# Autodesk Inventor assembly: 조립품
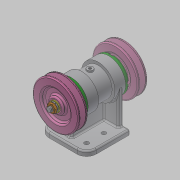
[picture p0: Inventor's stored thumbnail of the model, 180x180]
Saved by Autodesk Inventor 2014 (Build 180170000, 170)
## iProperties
Created: 2020-06
Part Number: 조립품
Document SubType Name: Assembly
Designer: NET
Author: NET
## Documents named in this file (12)
- C:\Users\NET\Desktop\700606V1053\조립품.iam
- C:\Users\NET\Desktop\700606V1053\본체.ipt
- C:\Users\NET\Desktop\700606V1053\V-벨트풀리.ipt
- C:\Users\NET\Desktop\700606V1053\너트 M10.ipt
- C:\Users\NET\Desktop\700606V1053\베어링 6204.ipt
- C:\Users\NET\Desktop\700606V1053\볼트 M4.ipt
- C:\Users\NET\Desktop\700606V1053\스프링 와셔 10.ipt
- C:\Users\NET\Desktop\700606V1053\오일 실 20 32 5.ipt
- C:\Users\NET\Desktop\700606V1053\축.ipt
- C:\Users\NET\Desktop\700606V1053\커버.ipt
- C:\Users\NET\Desktop\700606V1053\키 5x5x12.ipt
- C:\Users\NET\Desktop\700606V1053\평면 와셔 10x21.ipt
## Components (2 placed, 1 different names)
1. V-벨트풀리:1
2. V-벨트풀리:2
